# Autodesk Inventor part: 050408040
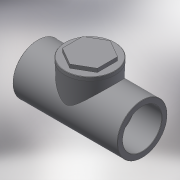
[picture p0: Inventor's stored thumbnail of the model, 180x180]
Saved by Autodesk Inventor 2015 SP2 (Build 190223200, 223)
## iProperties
Created: 2017-10
Part Number: 050408040
Material: Generic
Description: PLASSON CHECK VALVE T-CLAPPERALVE-CEMENT 40
Document SubType Name: Modeling
Designer: KIM
Density: 1 g/cm^3
Appearance: Default
Author: KIM
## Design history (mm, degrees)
derived "050408.ipt"
feature "Solid1::050408.ipt"
feature "Solid2::050408.ipt"
tag "TaggingFeature1"
body "Solid1"
other parameters: "d0" = 101, "d1" = 48, "d2" = 26, "d5" = 35.0568, "d7" = 0.38952, "d8" = 26, "d15" = 0, "d18" = 38.952, "d24" = 0.38952, "d37" = 33.6, "d38" = 4, "d39" = 0, "d41" = 48, "d42" = 4, "d43" = 45.6, "G_" = 38.952, "E_" = 48, "H_" = 101, "lt_" = 13, "l_" = 26
